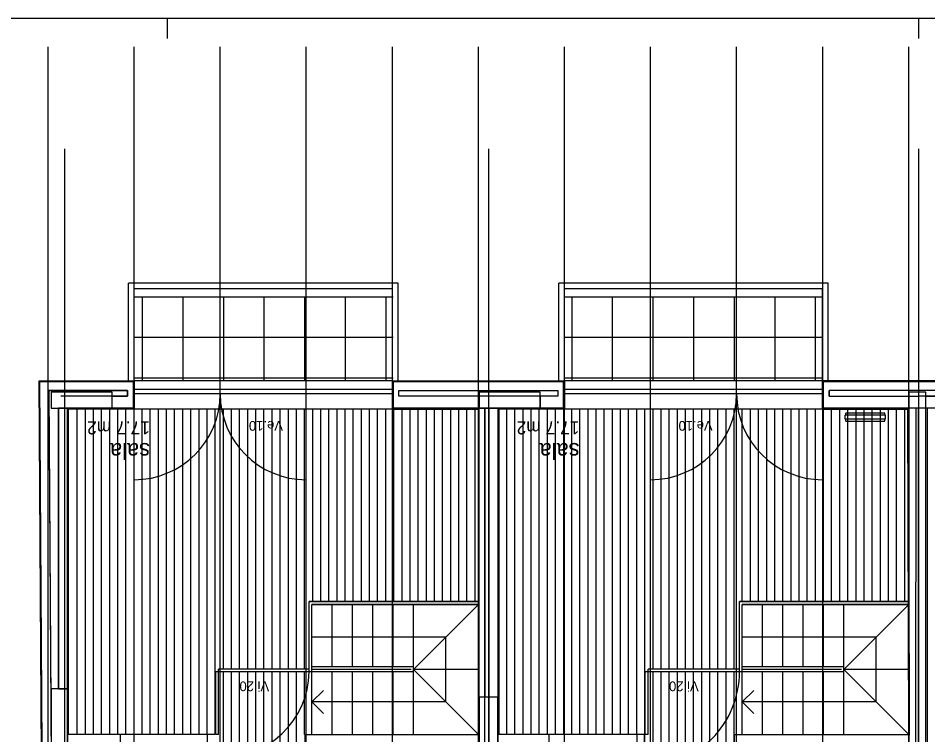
# Model space of a CAD drawing. Extents: x 1248 to 1356, y -443 to -224.
# Drawn here: x 1285.43 to 1296.63, y -232.79 to -223.96 of the extents above; entities that cross this region are included whole.
import ezdxf

# ---------------------------------------------------------------- set-up
doc = ezdxf.new("R2010")
doc.units = 0
for name, color, linetype in [('corte', 7, 'Continuous'), ('estereoctomias', 7, 'Continuous'), ('estrutura-eixos', 7, 'Continuous'), ('Level 1', 7, 'Continuous'), ('Level 10', 7, 'Continuous'), ('Level 13', 7, 'Continuous'), ('Level 2', 7, 'Continuous'), ('Level 4', 7, 'Continuous'), ('Level 40', 7, 'Continuous'), ('Level 60', 7, 'Continuous'), ('Level 62', 7, 'Continuous'), ('revestimentos', 7, 'Continuous'), ('vermelhos-cont', 7, 'Continuous'), ('vermelhos-tracej', 7, 'Continuous')]:
    doc.layers.add(name, color=color, linetype=linetype)

msp = doc.modelspace()

# ---------------------------------------------------------------- linework, layer by layer
at = {"layer": 'corte'}
for p, q in [((1285.693, -228.434), (1286.844, -228.434)), ((1285.763, -239.414), (1285.693, -228.434)), ((1285.804, -228.544), (1286.774, -228.544)), ((1295.413, -228.614), (1296.513, -228.614)), ((1285.923, -232.221), (1285.923, -228.764)), ((1296.109, -228.847), (1295.609, -228.847)), ((1295.609, -228.897), (1295.609, -228.847)), ((1296.099, -228.822), (1295.619, -228.822)), ((1295.619, -228.847), (1295.619, -228.822)), ((1296.099, -228.847), (1296.099, -228.822)), ((1296.109, -228.897), (1296.109, -228.847)), ((1296.109, -228.897), (1295.609, -228.897)), ((1295.619, -228.922), (1295.619, -228.897)), ((1295.619, -228.922), (1296.099, -228.922)), ((1296.099, -228.922), (1296.099, -228.897))]:
    msp.add_line(p, q, dxfattribs=at)
for points in [[(1286.583, -228.764), (1286.583, -228.564), (1285.833, -228.564), (1285.833, -228.764)], [(1291.854, -228.764), (1291.854, -228.564), (1291.104, -228.564), (1291.104, -228.764)], [(1296.605, -228.564), (1296.395, -228.564), (1296.395, -233.121), (1296.605, -233.121)], [(1285.833, -233.121), (1286.033, -233.121), (1286.033, -232.221), (1285.833, -232.221)], [(1291.104, -233.121), (1291.334, -233.121), (1291.334, -232.321), (1291.104, -232.321)]]:
    msp.add_lwpolyline(points, close=True, dxfattribs=at)
at = {"layer": 'estereoctomias'}
for points in [[(1286.844, -239.084), (1286.844, -239.414), (1285.763, -239.414), (1285.693, -228.434), (1286.844, -228.434), (1286.844, -228.764), (1286.583, -228.764), (1286.583, -228.614), (1286.774, -228.614), (1286.774, -228.544), (1285.804, -228.544), (1285.867, -238.371), (1285.833, -238.371), (1285.833, -239.271), (1285.872, -239.271), (1285.873, -239.304), (1286.774, -239.304), (1286.774, -239.234), (1286.033, -239.234), (1286.033, -239.084)], [(1291.854, -228.764), (1292.143, -228.764), (1292.143, -228.434), (1290.044, -228.434), (1290.044, -228.764), (1291.104, -228.764), (1291.104, -228.614), (1290.114, -228.614), (1290.114, -228.544), (1292.073, -228.544), (1292.073, -228.614), (1291.856, -228.614)], [(1298.263, -228.434), (1298.263, -228.764), (1296.605, -228.764), (1296.605, -228.614), (1298.193, -228.614), (1298.193, -228.544), (1295.413, -228.544), (1295.413, -228.614), (1296.395, -228.614), (1296.394, -228.764), (1295.343, -228.764), (1295.343, -228.434), (1298.263, -228.434)], [(1286.033, -228.764), (1285.923, -228.764), (1285.923, -232.221), (1286.033, -232.221)], [(1291.174, -228.764), (1291.174, -232.321), (1291.104, -232.321), (1291.104, -228.764)], [(1291.334, -232.321), (1291.224, -232.321), (1291.224, -228.764), (1291.334, -228.764)]]:
    msp.add_lwpolyline(points, close=True, dxfattribs=at)
at = {"layer": 'estrutura-eixos'}
for p, q in [((1287.266, -224.209), (1287.266, -223.959)), ((1296.516, -224.209), (1296.516, -223.959))]:
    msp.add_line(p, q, dxfattribs=at)
for centre, start, end in [((1286.854, -228.584), 270, 360), ((1288.974, -228.584), 180, 270), ((1293.213, -228.584), 270, 360), ((1295.333, -228.584), 180, 270)]:
    msp.add_arc(centre, 1.06, start, end, dxfattribs=at)
at = {"layer": 'Level 1'}
for p, q in [((1286.844, -228.434), (1286.844, -228.764)), ((1290.044, -228.764), (1290.044, -228.434)), ((1290.044, -228.434), (1292.143, -228.434)), ((1292.143, -228.434), (1292.143, -228.764)), ((1295.343, -228.764), (1295.343, -228.434)), ((1298.263, -228.434), (1295.343, -228.434)), ((1285.804, -228.544), (1285.873, -239.304)), ((1286.774, -228.614), (1285.953, -228.614)), ((1286.774, -228.544), (1286.774, -228.614)), ((1290.114, -228.544), (1292.073, -228.544)), ((1290.114, -228.614), (1290.114, -228.544)), ((1292.073, -228.614), (1290.114, -228.614)), ((1292.073, -228.544), (1292.073, -228.614)), ((1296.494, -228.544), (1295.413, -228.544)), ((1295.413, -228.614), (1295.413, -228.544)), ((1298.193, -228.544), (1296.493, -228.544)), ((1298.193, -228.614), (1296.513, -228.614)), ((1286.033, -228.764), (1286.033, -233.114)), ((1286.844, -228.764), (1286.033, -228.764)), ((1292.143, -228.764), (1290.044, -228.764)), ((1291.104, -232.79), (1291.104, -228.764)), ((1291.174, -239.234), (1291.174, -228.764)), ((1291.224, -228.764), (1291.224, -239.084)), ((1291.334, -228.764), (1291.334, -233.044)), ((1295.343, -228.764), (1296.394, -228.764)), ((1296.404, -232.79), (1296.394, -228.764)), ((1298.263, -228.764), (1296.394, -228.764)), ((1296.473, -239.084), (1296.483, -228.764)), ((1296.513, -239.084), (1296.513, -228.764)), ((1296.623, -239.084), (1296.623, -228.764))]:
    msp.add_line(p, q, dxfattribs=at)
at = {"layer": 'Level 10'}
for p, q in [((1290.043, -227.394), (1286.863, -227.394)), ((1286.953, -227.394), (1286.953, -228.424)), ((1287.453, -227.394), (1287.453, -228.424)), ((1287.953, -227.394), (1287.953, -228.424)), ((1288.453, -227.394), (1288.453, -228.424)), ((1288.953, -227.394), (1288.953, -228.424)), ((1289.453, -227.394), (1289.453, -228.424)), ((1289.953, -227.394), (1289.953, -228.424)), ((1295.333, -227.394), (1292.153, -227.394)), ((1292.243, -227.394), (1292.243, -228.424)), ((1292.743, -227.394), (1292.743, -228.424)), ((1293.243, -227.394), (1293.243, -228.424)), ((1293.743, -227.394), (1293.743, -228.424)), ((1294.243, -227.394), (1294.243, -228.424)), ((1294.743, -227.394), (1294.743, -228.424)), ((1295.243, -227.394), (1295.243, -228.424)), ((1290.043, -227.894), (1286.863, -227.894)), ((1295.333, -227.894), (1292.153, -227.894)), ((1290.043, -228.394), (1286.863, -228.394)), ((1295.333, -228.394), (1292.153, -228.394)), ((1286.153, -232.78), (1286.153, -228.774)), ((1286.253, -232.78), (1286.253, -228.774)), ((1286.353, -232.78), (1286.353, -228.774)), ((1286.453, -232.78), (1286.453, -228.774)), ((1286.553, -232.78), (1286.553, -228.774)), ((1286.653, -232.78), (1286.653, -228.774)), ((1286.753, -232.78), (1286.753, -228.774)), ((1286.853, -232.78), (1286.853, -228.774)), ((1286.953, -232.78), (1286.953, -228.774)), ((1287.053, -232.78), (1287.053, -228.774)), ((1287.153, -232.78), (1287.153, -228.774)), ((1287.253, -232.78), (1287.253, -228.774)), ((1287.353, -232.78), (1287.353, -228.774)), ((1287.453, -232.78), (1287.453, -228.774)), ((1287.553, -232.78), (1287.553, -228.774)), ((1287.653, -232.78), (1287.653, -228.774)), ((1287.753, -232.78), (1287.753, -228.774)), ((1287.853, -232.78), (1287.853, -228.774)), ((1287.953, -231.975), (1287.953, -228.774)), ((1288.053, -231.975), (1288.053, -228.774)), ((1288.153, -231.975), (1288.153, -228.774)), ((1288.253, -231.975), (1288.253, -228.774)), ((1288.353, -231.975), (1288.353, -228.774)), ((1288.453, -231.975), (1288.453, -228.774)), ((1288.553, -231.975), (1288.553, -228.774)), ((1288.653, -231.975), (1288.653, -228.774)), ((1288.753, -231.975), (1288.753, -228.774)), ((1288.853, -231.975), (1288.853, -228.774)), ((1288.953, -231.975), (1288.953, -228.774)), ((1289.053, -231.145), (1289.053, -228.774)), ((1289.153, -231.145), (1289.153, -228.774)), ((1289.253, -231.145), (1289.253, -228.774)), ((1289.353, -231.145), (1289.353, -228.774)), ((1289.453, -231.145), (1289.453, -228.774)), ((1289.553, -231.145), (1289.553, -228.774)), ((1289.653, -231.145), (1289.653, -228.774)), ((1289.753, -231.145), (1289.753, -228.774)), ((1289.853, -231.145), (1289.853, -228.774)), ((1289.953, -231.145), (1289.953, -228.774)), ((1290.053, -231.145), (1290.053, -228.774)), ((1290.153, -231.145), (1290.153, -228.774)), ((1290.253, -231.145), (1290.253, -228.774)), ((1290.353, -231.145), (1290.353, -228.774)), ((1290.453, -231.145), (1290.453, -228.774)), ((1290.553, -231.145), (1290.553, -228.774)), ((1290.653, -231.145), (1290.653, -228.774)), ((1290.753, -231.145), (1290.753, -228.774)), ((1290.853, -231.145), (1290.853, -228.774)), ((1290.953, -231.145), (1290.953, -228.774)), ((1291.053, -231.145), (1291.053, -228.774)), ((1291.444, -232.78), (1291.444, -228.774)), ((1291.544, -232.78), (1291.544, -228.774)), ((1291.644, -232.78), (1291.644, -228.774)), ((1291.744, -232.78), (1291.744, -228.774)), ((1291.844, -232.78), (1291.844, -228.774)), ((1291.944, -232.78), (1291.944, -228.774)), ((1292.044, -232.78), (1292.044, -228.774)), ((1292.144, -232.78), (1292.144, -228.774)), ((1292.244, -232.78), (1292.244, -228.774)), ((1292.344, -232.78), (1292.344, -228.774)), ((1292.444, -232.78), (1292.444, -228.774)), ((1292.544, -232.78), (1292.544, -228.774)), ((1292.644, -232.78), (1292.644, -228.774)), ((1292.744, -232.78), (1292.744, -228.774)), ((1292.844, -232.78), (1292.844, -228.774)), ((1292.944, -232.78), (1292.944, -228.774)), ((1293.044, -232.78), (1293.044, -228.774)), ((1293.144, -233.532), (1293.144, -228.774)), ((1293.244, -231.975), (1293.244, -228.774)), ((1293.344, -231.975), (1293.344, -228.774)), ((1293.444, -231.975), (1293.444, -228.774)), ((1293.544, -231.975), (1293.544, -228.774)), ((1293.644, -231.975), (1293.644, -228.774)), ((1293.744, -231.975), (1293.744, -228.774)), ((1293.844, -231.975), (1293.844, -228.774)), ((1293.944, -231.975), (1293.944, -228.774)), ((1294.044, -231.975), (1294.044, -228.774)), ((1294.144, -231.975), (1294.144, -228.774)), ((1294.244, -231.975), (1294.244, -228.774)), ((1294.344, -231.145), (1294.344, -228.774)), ((1294.444, -231.145), (1294.444, -228.774)), ((1294.544, -231.145), (1294.544, -228.774)), ((1294.644, -231.145), (1294.644, -228.774)), ((1294.744, -231.145), (1294.744, -228.774)), ((1294.844, -231.145), (1294.844, -228.774)), ((1294.944, -231.145), (1294.944, -228.774)), ((1295.044, -231.145), (1295.044, -228.774)), ((1295.144, -231.145), (1295.144, -228.774)), ((1295.244, -231.145), (1295.244, -228.774)), ((1295.344, -231.145), (1295.344, -228.774)), ((1295.444, -231.145), (1295.444, -228.774)), ((1295.544, -231.145), (1295.544, -228.774)), ((1295.644, -231.145), (1295.644, -228.774)), ((1295.744, -231.145), (1295.744, -228.774)), ((1295.844, -231.145), (1295.844, -228.774)), ((1295.944, -231.145), (1295.944, -228.774)), ((1296.044, -231.145), (1296.044, -228.774)), ((1296.144, -231.145), (1296.144, -228.774)), ((1296.244, -231.145), (1296.244, -228.774)), ((1296.344, -231.145), (1296.344, -228.774)), ((1287.953, -233.575), (1287.953, -232.01)), ((1288.053, -233.575), (1288.053, -232.01)), ((1288.153, -233.575), (1288.153, -232.01)), ((1288.253, -233.575), (1288.253, -232.01)), ((1288.353, -233.575), (1288.353, -232.01)), ((1288.453, -233.575), (1288.453, -232.01)), ((1288.553, -233.575), (1288.553, -232.01)), ((1288.653, -233.575), (1288.653, -232.01)), ((1288.753, -233.575), (1288.753, -232.01)), ((1288.853, -233.575), (1288.853, -232.01)), ((1288.953, -232.78), (1288.953, -232.01)), ((1293.244, -233.532), (1293.244, -232.01)), ((1293.344, -233.532), (1293.344, -232.01)), ((1293.444, -233.532), (1293.444, -232.01)), ((1293.544, -233.532), (1293.544, -232.01)), ((1293.644, -233.532), (1293.644, -232.01)), ((1293.744, -233.532), (1293.744, -232.01)), ((1293.844, -233.532), (1293.844, -232.01)), ((1293.944, -233.532), (1293.944, -232.01)), ((1294.044, -233.532), (1294.044, -232.01)), ((1294.144, -233.532), (1294.144, -232.01)), ((1294.244, -233.929), (1294.244, -232.01)), ((1287.759, -232.78), (1286.683, -232.78)), ((1293.049, -232.78), (1291.963, -232.78))]:
    msp.add_line(p, q, dxfattribs=at)
at = {"layer": 'Level 13'}
for p, q in [((1291.094, -231.145), (1289.009, -231.145)), ((1289.009, -232.01), (1289.009, -231.145)), ((1289.009, -231.145), (1291.094, -231.145)), ((1289.009, -231.975), (1289.009, -231.145)), ((1291.094, -231.18), (1289.044, -231.18)), ((1289.044, -232.01), (1289.044, -231.18)), ((1289.044, -231.18), (1291.094, -231.18)), ((1289.044, -232.01), (1289.044, -231.18)), ((1296.394, -231.145), (1294.309, -231.145)), ((1294.309, -232.01), (1294.309, -231.145)), ((1294.309, -231.145), (1296.394, -231.145)), ((1294.309, -231.975), (1294.309, -231.145)), ((1296.394, -231.18), (1294.344, -231.18)), ((1294.344, -232.01), (1294.344, -231.18)), ((1294.344, -231.18), (1296.394, -231.18)), ((1294.344, -232.01), (1294.344, -231.18)), ((1289.009, -231.975), (1287.894, -231.975)), ((1287.894, -232.78), (1287.894, -231.975)), ((1293.184, -232.78), (1293.184, -231.975)), ((1294.309, -231.975), (1293.184, -231.975)), ((1289.044, -232.01), (1287.859, -232.01)), ((1287.859, -232.78), (1287.859, -232.01)), ((1294.344, -232.01), (1293.149, -232.01)), ((1293.149, -232.78), (1293.149, -232.01)), ((1287.894, -232.78), (1287.859, -232.78)), ((1293.184, -232.78), (1293.149, -232.78))]:
    msp.add_line(p, q, dxfattribs=at)
at = {"layer": 'Level 2'}
for p, q in [((1286.784, -228.424), (1286.784, -227.224)), ((1290.104, -227.224), (1286.784, -227.224)), ((1290.104, -228.424), (1290.104, -227.224)), ((1292.083, -228.424), (1292.083, -227.224)), ((1295.403, -227.224), (1292.083, -227.224)), ((1295.403, -228.424), (1295.403, -227.224)), ((1290.034, -227.294), (1286.854, -227.294)), ((1286.854, -228.424), (1286.854, -227.294)), ((1290.034, -228.424), (1290.034, -227.294)), ((1295.333, -227.294), (1292.153, -227.294)), ((1292.153, -228.424), (1292.153, -227.294)), ((1295.333, -228.424), (1295.333, -227.294)), ((1290.034, -228.424), (1286.854, -228.424)), ((1295.333, -228.424), (1292.153, -228.424)), ((1290.034, -228.534), (1286.854, -228.534)), ((1290.034, -228.584), (1286.854, -228.584)), ((1295.333, -228.534), (1292.153, -228.534)), ((1295.333, -228.584), (1292.153, -228.584)), ((1290.034, -228.774), (1286.854, -228.774)), ((1295.333, -228.774), (1292.153, -228.774)), ((1289.294, -231.95), (1289.294, -231.18)), ((1289.544, -231.95), (1289.544, -231.18)), ((1289.794, -231.95), (1289.794, -231.18)), ((1290.044, -231.95), (1290.044, -231.18)), ((1290.294, -231.95), (1290.294, -231.18)), ((1290.294, -231.98), (1291.094, -231.18)), ((1294.594, -231.95), (1294.594, -231.18)), ((1294.844, -231.95), (1294.844, -231.18)), ((1295.094, -231.95), (1295.094, -231.18)), ((1295.344, -231.95), (1295.344, -231.18)), ((1295.594, -231.95), (1295.594, -231.18)), ((1295.594, -231.98), (1296.394, -231.18)), ((1289.044, -231.58), (1290.694, -231.58)), ((1290.694, -232.38), (1290.694, -231.58)), ((1294.344, -231.58), (1295.994, -231.58)), ((1295.994, -232.38), (1295.994, -231.58)), ((1290.294, -231.95), (1289.044, -231.95)), ((1290.265, -231.98), (1289.044, -231.98)), ((1290.294, -232.01), (1290.294, -231.95)), ((1291.094, -231.98), (1290.294, -231.98)), ((1290.294, -231.98), (1291.094, -232.78)), ((1295.594, -231.95), (1294.344, -231.95)), ((1295.564, -231.98), (1294.344, -231.98)), ((1295.594, -232.01), (1295.594, -231.95)), ((1296.394, -231.98), (1295.594, -231.98)), ((1295.594, -231.98), (1296.394, -232.78)), ((1290.294, -232.01), (1289.044, -232.01)), ((1289.044, -232.78), (1289.044, -232.01)), ((1289.294, -232.78), (1289.294, -232.01)), ((1289.544, -232.78), (1289.544, -232.01)), ((1289.794, -232.78), (1289.794, -232.01)), ((1290.044, -232.78), (1290.044, -232.01)), ((1290.294, -232.78), (1290.294, -232.01)), ((1295.594, -232.01), (1294.344, -232.01)), ((1294.344, -232.78), (1294.344, -232.01)), ((1294.594, -232.78), (1294.594, -232.01)), ((1294.844, -232.78), (1294.844, -232.01)), ((1295.094, -232.78), (1295.094, -232.01)), ((1295.344, -232.78), (1295.344, -232.01)), ((1295.594, -232.78), (1295.594, -232.01)), ((1289.186, -232.239), (1289.044, -232.38)), ((1294.485, -232.239), (1294.344, -232.38)), ((1290.694, -232.38), (1289.044, -232.38)), ((1289.186, -232.522), (1289.044, -232.38)), ((1295.994, -232.38), (1294.344, -232.38)), ((1294.485, -232.522), (1294.344, -232.38))]:
    msp.add_line(p, q, dxfattribs=at)
at = {"layer": 'Level 4'}
msp.add_arc((1293.144, -232.01), 1.165, 270, 0.001, dxfattribs=at)
msp.add_ellipse((1287.844, -232.01), major_axis=(-1.165, 0), ratio=0.93133, start_param=1.578735, end_param=3.141609, dxfattribs=at)
at = {"layer": 'Level 62'}
msp.add_lwpolyline([(1355.966, -223.959), (1355.966, -253.659), (1278.016, -253.659), (1278.016, -223.959)], close=True, dxfattribs=at)
at = {"layer": 'revestimentos'}
for p, q in [((1285.683, -228.424), (1286.854, -228.424)), ((1285.753, -239.424), (1285.683, -228.424)), ((1286.854, -228.424), (1286.854, -228.774)), ((1290.034, -228.424), (1292.153, -228.424)), ((1290.034, -228.774), (1290.034, -228.424)), ((1292.153, -228.424), (1292.153, -228.774)), ((1296.474, -228.424), (1295.333, -228.424)), ((1295.333, -228.774), (1295.333, -228.424)), ((1298.273, -228.424), (1296.474, -228.424)), ((1286.854, -228.774), (1286.043, -228.774)), ((1286.043, -228.774), (1286.043, -232.78)), ((1290.034, -228.774), (1291.094, -228.774)), ((1291.094, -232.78), (1291.094, -228.774)), ((1292.153, -228.774), (1291.344, -228.774)), ((1291.344, -228.774), (1291.344, -232.78)), ((1295.333, -228.774), (1296.384, -228.774)), ((1296.394, -232.78), (1296.384, -228.774)), ((1286.683, -232.78), (1286.043, -232.78)), ((1286.683, -232.78), (1286.683, -233.034)), ((1287.849, -232.78), (1287.759, -232.78)), ((1287.759, -233.034), (1287.759, -232.78)), ((1288.958, -232.78), (1291.094, -232.78)), ((1288.959, -233.939), (1288.959, -232.78)), ((1291.963, -232.78), (1291.344, -232.78)), ((1291.963, -232.78), (1291.963, -233.034)), ((1293.049, -233.034), (1293.049, -232.78)), ((1293.139, -232.78), (1293.049, -232.78)), ((1293.139, -234.904), (1293.139, -232.78)), ((1294.249, -232.78), (1296.394, -232.78)), ((1294.249, -233.939), (1294.249, -232.78))]:
    msp.add_line(p, q, dxfattribs=at)
at = {"layer": 'vermelhos-cont'}
for p, q in [((1285.998, -225.567), (1285.998, -250.792)), ((1291.219, -225.567), (1291.219, -250.792)), ((1296.519, -250.792), (1296.519, -225.567))]:
    msp.add_line(p, q, dxfattribs=at)
at = {"layer": 'vermelhos-tracej'}
for p, q in [((1285.794, -234.928), (1285.794, -224.312)), ((1286.854, -234.928), (1286.854, -224.312)), ((1287.914, -234.928), (1287.914, -224.312)), ((1288.974, -234.928), (1288.974, -224.312)), ((1290.034, -234.928), (1290.034, -224.312)), ((1291.094, -234.928), (1291.094, -224.312)), ((1292.154, -234.928), (1292.154, -224.312)), ((1293.214, -234.928), (1293.214, -224.312)), ((1294.274, -234.928), (1294.274, -224.312)), ((1295.334, -234.928), (1295.334, -224.312)), ((1296.394, -234.928), (1296.394, -224.312))]:
    msp.add_line(p, q, dxfattribs=at)

# ---------------------------------------------------------------- texts
at = {"layer": 'Level 40'}
for s, p in [('Ve.10', (1288.687, -228.92)), ('Ve.10', (1293.978, -228.92)), ('Vi.20', (1288.517, -232.128)), ('Vi.20', (1293.807, -232.128))]:
    msp.add_text(s, height=0.12, rotation=180, dxfattribs=at).set_placement(p)
at = {"layer": 'Level 60'}
for s, height, p in [('17.7 m2', 0.16, (1287.048, -228.925)), ('17.7 m2', 0.16, (1292.338, -228.925)), ('sala', 0.2, (1287.048, -229.192)), ('sala', 0.2, (1292.338, -229.192))]:
    msp.add_text(s, height=height, rotation=180, dxfattribs=at).set_placement(p)

doc.saveas('drawing.dxf')
